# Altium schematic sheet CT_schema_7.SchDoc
size 278 x 170 mm
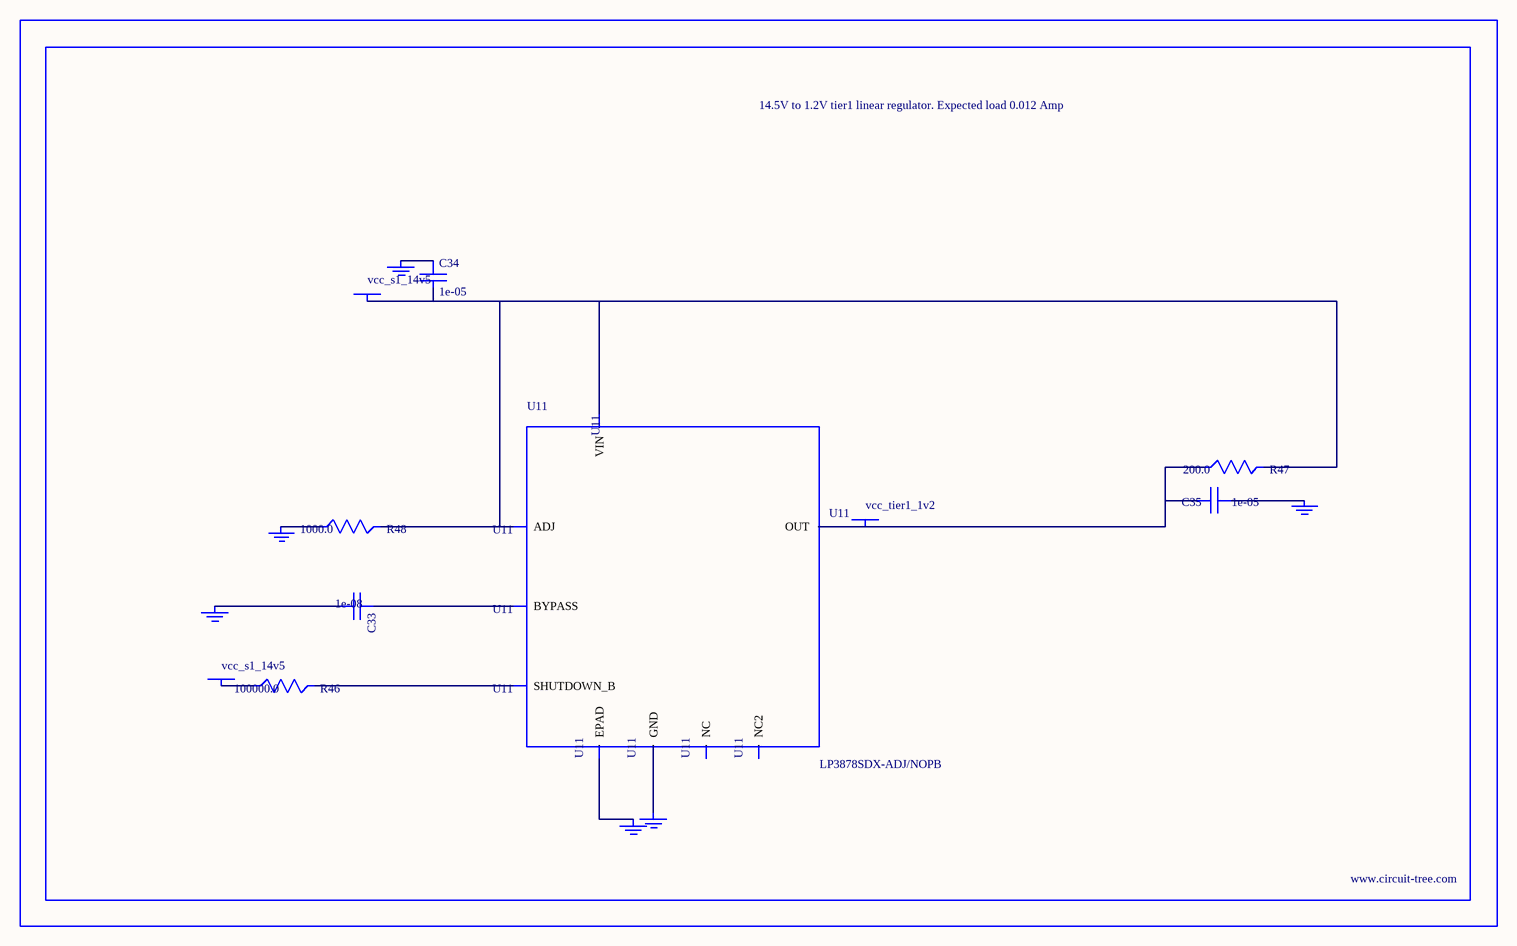
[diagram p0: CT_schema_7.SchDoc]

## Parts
BORDER6  (no value)
C33  1e-08  [C0402]
C34  1e-05  [C1210]
C35  1e-05  [C0805]
GND_INSTANCE_6_0  (no value)
GND_INSTANCE_6_1  (no value)
GND_INSTANCE_6_2  (no value)
GND_INSTANCE_6_3  (no value)
GND_INSTANCE_6_4  (no value)
GND_INSTANCE_6_5  (no value)
POWER_INSTANCE_6_0  vcc_s1_14v5
POWER_INSTANCE_6_1  vcc_s1_14v5
POWER_INSTANCE_6_2  vcc_tier1_1v2
R46  100000.0  [R0603]
R47  200.0  [R0603]
R48  1000.0  [R0603]
U11  LP3878SDX-ADJ/NOPB  [WSON-8]

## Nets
NetC33_1: C33.1 U11.1(BYPASS)
NetC33_2: C33.2 GND_INSTANCE_6_0.0(GND)
NetC34_1: C34.1 GND_INSTANCE_6_1.0(GND)
NetC34_2: C34.2 POWER_INSTANCE_6_0.0(PWR) R47.2 R48.2 U11.4(VIN) U11.6(ADJ)
NetC35_1: C35.1 GND_INSTANCE_6_2.0(GND)
NetC35_2: C35.2 POWER_INSTANCE_6_2.0(PWR) R47.1 U11.5(OUT)
NetGND_INSTANCE_6_3_0: GND_INSTANCE_6_3.0(GND) R48.1
NetGND_INSTANCE_6_4_0: GND_INSTANCE_6_4.0(GND) U11.PAD(EPAD)
NetGND_INSTANCE_6_5_0: GND_INSTANCE_6_5.0(GND) U11.3(GND)
NetPOWER_INSTANCE_6_1_0: POWER_INSTANCE_6_1.0(PWR) R46.1
NetR46_2: R46.2 U11.8(SHUTDOWN_B)

Not connected (* = marked no-connect by the designer): U11 2(NC) 7(NC2)

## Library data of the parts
BORDER6 = BORDER_PAGE6
C33 = C0402C103K3RAC
C34 = C1210C106K5PACTU
C35 = GRM219R60J106ME19D
GND_INSTANCE_6_0-GND_INSTANCE_6_5 = GND
POWER_INSTANCE_6_0-POWER_INSTANCE_6_2 = PWR
R46 = RC0603JR-07100KL
R47 = RC0603JR-07200RL
R48 = RC0603JR-071KL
